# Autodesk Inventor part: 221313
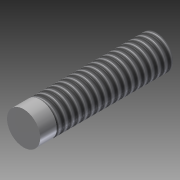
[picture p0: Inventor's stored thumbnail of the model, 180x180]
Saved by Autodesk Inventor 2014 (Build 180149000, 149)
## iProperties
Shininess: 20.0
Length Units: 11272
Angle Units: 11279
Time Units: 11290
Mass Units: 11286
Length Display Precision: 3
Angle Display Precision: 2
Company: Autodesk, Inc.
Created: 2002-07
Part Number: 221313
Material: Steel, Mild
Description: STUD, WELD; 1/4" NC x 1" BW W/FERRULES
Document SubType Name: Modeling
Designer: Autodesk, Inc.
Density: 7.86 g/cm^3
Appearance: Steel
Density: 0.0
Volumn: 0.0
Area: 0.0
PropertySet Name: Model Information
Control State: 0
Master: False
Checked Out: False
Last Check In By: JT
Last Check In Date: 2003-06-20
Title: STUD, WELD; 1/4" NC x 1" BW W/FERRULES
Author: Autodesk, Inc.
Comments: Pre-welded Length = 1.00" Post-weld Length = 0.875"
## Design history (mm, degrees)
sketch "Sketch1"
  geometry: C1 r 3.175 at (0, 0); 1 further point
  constraints: 1 centre point, 1 coincident
  dimensions: "d3" = 6.35 diameter of C1 (= Diameter)
extrude "Extrusion2" new body sketch "Sketch1" distance "d4" = 25.4 (= OAL); taper "d5" = 0 deg
thread "Thread1" dims "d7" = 0, "Thread_Length" = 22.225 (computed from OAL)
body "Solid1"
other parameters: "Diameter" = 6.35 [user parameter; used in 1 equation term], "OAL" = 25.4 [user parameter; used in 2 equation terms]
